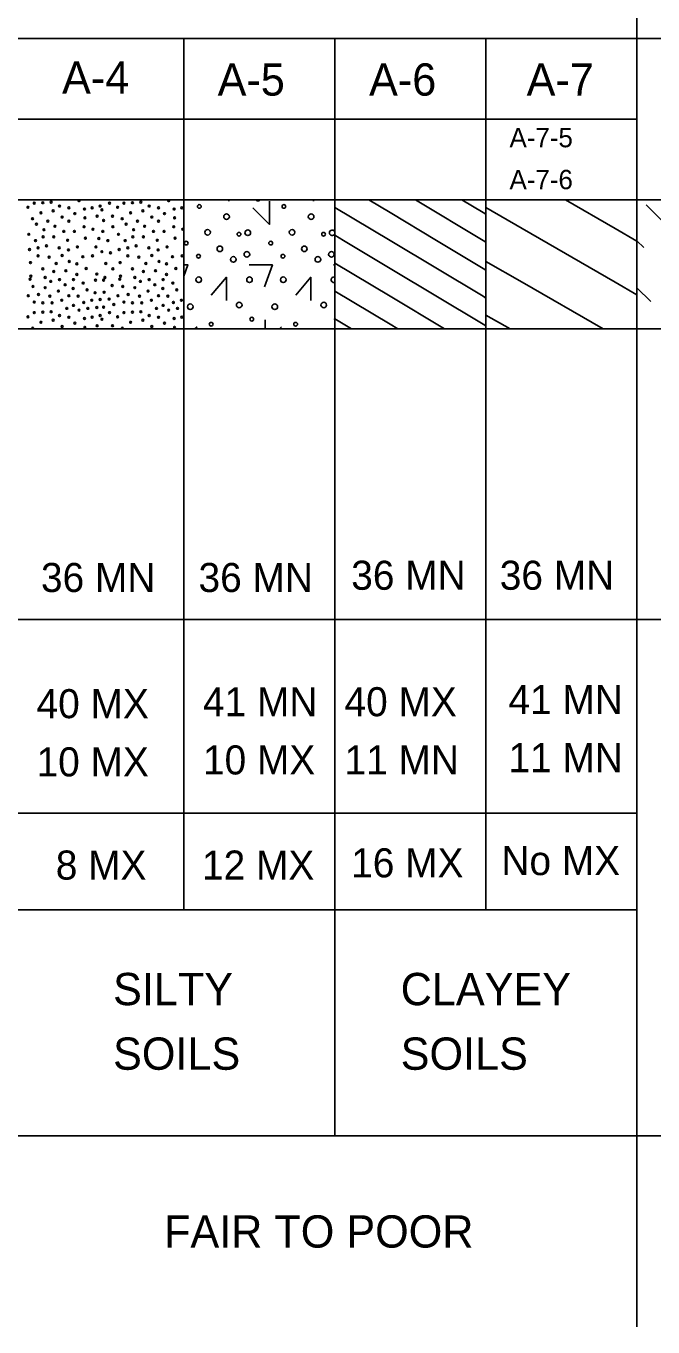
# Model space of a CAD drawing. Extents: x 278710 to 279187, y 171464 to 171625.
# Drawn here: x 279023.58 to 279032.01, y 171537.45 to 171554.93 of the extents above; entities that cross this region are included whole.
import ezdxf

# ---------------------------------------------------------------- set-up
doc = ezdxf.new("R2010")
doc.units = 0
doc.layers.add('Geotech Sheets and Borders Cell', color=7, linetype='Continuous')

msp = doc.modelspace()

# ---------------------------------------------------------------- linework, layer by layer
at = {"layer": 'Geotech Sheets and Borders Cell'}
for p, q in [((279031.791, 171556.932), (279031.791, 171537.446)), ((279031.791, 171556.932), (279031.791, 171552.486)), ((279005.33, 171554.763), (279043.07, 171554.763)), ((279025.701, 171543.051), (279025.701, 171554.763)), ((279027.731, 171548.529), (279027.731, 171554.763)), ((279029.761, 171543.051), (279029.761, 171554.763)), ((279009.451, 171553.679), (279031.791, 171553.679)), ((279005.33, 171552.594), (279043.07, 171552.594)), ((279027.731, 171552.493), (279028.473, 171552.048)), ((279028.188, 171552.594), (279028.473, 171552.423)), ((279028.813, 171552.594), (279029.723, 171552.048)), ((279029.438, 171552.594), (279029.723, 171552.423)), ((279030.247, 171552.209), (279029.761, 171552.49)), ((279031.497, 171552.209), (279030.831, 171552.594)), ((279031.791, 171546.955), (279031.791, 171552.464)), ((279032.125, 171552.316), (279031.913, 171552.529)), ((279028.473, 171552.423), (279029.097, 171552.048)), ((279029.723, 171552.423), (279029.761, 171552.4)), ((279027.731, 171552.118), (279027.847, 171552.048)), ((279031.497, 171551.487), (279030.247, 171552.209)), ((279031.791, 171552.04), (279031.497, 171552.209)), ((279027.847, 171552.048), (279028.473, 171551.673)), ((279028.473, 171552.048), (279029.723, 171551.298)), ((279029.097, 171552.048), (279029.723, 171551.673)), ((279029.723, 171552.048), (279029.761, 171552.025)), ((279031.883, 171551.952), (279031.791, 171552.043)), ((279027.731, 171551.743), (279028.473, 171551.298)), ((279030.247, 171551.487), (279029.761, 171551.768)), ((279028.473, 171551.673), (279029.723, 171550.923)), ((279029.723, 171551.673), (279029.761, 171551.65)), ((279031.335, 171550.859), (279030.247, 171551.487)), ((279031.791, 171551.318), (279031.497, 171551.487)), ((279031.978, 171551.228), (279031.791, 171551.414)), ((279027.731, 171551.368), (279028.473, 171550.923)), ((279028.473, 171551.298), (279029.204, 171550.859)), ((279029.723, 171551.298), (279029.761, 171551.275)), ((279030.085, 171550.859), (279029.761, 171551.046)), ((279005.33, 171550.859), (279043.07, 171550.859)), ((279027.731, 171550.993), (279027.954, 171550.859)), ((279028.473, 171550.923), (279028.579, 171550.859)), ((279029.723, 171550.923), (279029.761, 171550.9)), ((279027.731, 171540.014), (279027.731, 171548.703)), ((279005.33, 171546.955), (279043.07, 171546.955)), ((279005.33, 171544.352), (279031.791, 171544.352)), ((279005.33, 171543.051), (279031.791, 171543.051)), ((279005.33, 171540.014), (279043.07, 171540.014))]:
    msp.add_line(p, q, dxfattribs=at)
for points in [[(279026.306, 171552.576), (279026.306, 171552.594)], [(279026.851, 171552.576), (279026.851, 171552.264), (279026.629, 171552.485)], [(279027.442, 171552.576), (279027.442, 171552.594)], [(279025.701, 171551.719), (279025.756, 171551.719), (279025.701, 171551.567)], [(279026.579, 171551.719), (279026.892, 171551.719), (279026.784, 171551.425)], [(279027.715, 171551.719), (279027.731, 171551.719)], [(279026.273, 171551.242), (279026.273, 171551.555), (279026.071, 171551.315)], [(279027.408, 171551.242), (279027.408, 171551.555), (279027.207, 171551.315)], [(279025.85, 171550.859), (279025.88, 171550.889)], [(279026.794, 171550.98), (279026.794, 171550.859)], [(279026.986, 171550.859), (279027.016, 171550.889)]]:
    msp.add_lwpolyline(points, dxfattribs=at)
for centre, radius in [((279023.607, 171552.494), 0.0125), ((279023.692, 171552.551), 0.0125), ((279023.782, 171552.42), 0.0125), ((279023.806, 171552.556), 0.0125), ((279023.919, 171552.562), 0.0125), ((279023.947, 171552.448), 0.0125), ((279024.032, 171552.511), 0.0125), ((279024.157, 171552.487), 0.0125), ((279024.367, 171552.471), 0.0125), ((279024.469, 171552.488), 0.0125), ((279024.577, 171552.511), 0.0125), ((279024.602, 171552.46), 0.0125), ((279024.704, 171552.551), 0.0125), ((279024.812, 171552.494), 0.0125), ((279024.897, 171552.551), 0.0125), ((279024.987, 171552.42), 0.0125), ((279025.011, 171552.556), 0.0125), ((279025.124, 171552.562), 0.0125), ((279025.152, 171552.448), 0.0125), ((279025.237, 171552.511), 0.0125), ((279025.362, 171552.487), 0.0125), ((279025.572, 171552.471), 0.0125), ((279025.674, 171552.488), 0.0125), ((279025.91, 171552.506), 0.025), ((279027.046, 171552.506), 0.025), ((279023.669, 171552.341), 0.0125), ((279023.721, 171552.267), 0.0125), ((279023.874, 171552.307), 0.0125), ((279024.066, 171552.363), 0.0125), ((279024.157, 171552.307), 0.0125), ((279024.237, 171552.409), 0.0125), ((279024.373, 171552.352), 0.0125), ((279024.537, 171552.374), 0.0125), ((279024.624, 171552.318), 0.0125), ((279024.744, 171552.374), 0.0125), ((279024.874, 171552.341), 0.0125), ((279024.926, 171552.267), 0.0125), ((279025.079, 171552.307), 0.0125), ((279025.271, 171552.363), 0.0125), ((279025.362, 171552.307), 0.0125), ((279025.442, 171552.409), 0.0125), ((279025.578, 171552.352), 0.0125), ((279026.276, 171552.368), 0.0375), ((279027.412, 171552.368), 0.0375), ((279023.618, 171552.131), 0.0125), ((279023.811, 171552.097), 0.0125), ((279023.822, 171552.193), 0.0125), ((279023.953, 171552.097), 0.0125), ((279023.97, 171552.239), 0.0125), ((279024.089, 171552.171), 0.0125), ((279024.231, 171552.171), 0.0125), ((279024.361, 171552.233), 0.0125), ((279024.379, 171552.079), 0.0125), ((279024.481, 171552.199), 0.0125), ((279024.56, 171552.074), 0.0125), ((279024.613, 171552.171), 0.0125), ((279024.749, 171552.233), 0.0125), ((279024.823, 171552.131), 0.0125), ((279025.016, 171552.097), 0.0125), ((279025.027, 171552.193), 0.0125), ((279025.158, 171552.097), 0.0125), ((279025.175, 171552.239), 0.0125), ((279025.294, 171552.171), 0.0125), ((279025.436, 171552.171), 0.0125), ((279025.566, 171552.233), 0.0125), ((279025.584, 171552.079), 0.0125), ((279025.686, 171552.199), 0.0125), ((279026.021, 171552.158), 0.0375), ((279026.443, 171552.132), 0.025), ((279026.561, 171552.152), 0.0375), ((279027.156, 171552.158), 0.0375), ((279027.579, 171552.132), 0.025), ((279023.629, 171551.926), 0.0125), ((279023.709, 171552.046), 0.0125), ((279023.743, 171551.949), 0.0125), ((279023.856, 171551.977), 0.0125), ((279024.027, 171551.949), 0.0125), ((279024.14, 171552.051), 0.0125), ((279024.151, 171551.921), 0.0125), ((279024.271, 171551.961), 0.0125), ((279024.521, 171551.961), 0.0125), ((279024.602, 171551.898), 0.0125), ((279024.681, 171552.046), 0.0125), ((279024.834, 171551.926), 0.0125), ((279024.914, 171552.046), 0.0125), ((279024.948, 171551.949), 0.0125), ((279025.061, 171551.977), 0.0125), ((279025.232, 171551.949), 0.0125), ((279025.345, 171552.051), 0.0125), ((279025.356, 171551.921), 0.0125), ((279025.476, 171551.961), 0.0125), ((279025.734, 171552.013), 0.025), ((279026.186, 171551.936), 0.0375), ((279026.869, 171552.013), 0.025), ((279027.321, 171551.936), 0.0375), ((279023.641, 171551.751), 0.0125), ((279023.743, 171551.841), 0.0125), ((279023.891, 171551.824), 0.0125), ((279023.987, 171551.739), 0.0125), ((279024.066, 171551.847), 0.0125), ((279024.163, 171551.767), 0.0125), ((279024.265, 171551.734), 0.0125), ((279024.344, 171551.83), 0.0125), ((279024.475, 171551.841), 0.0125), ((279024.653, 171551.739), 0.0125), ((279024.716, 171551.881), 0.0125), ((279024.846, 171551.751), 0.0125), ((279024.948, 171551.841), 0.0125), ((279025.096, 171551.824), 0.0125), ((279025.192, 171551.739), 0.0125), ((279025.271, 171551.847), 0.0125), ((279025.368, 171551.767), 0.0125), ((279025.47, 171551.734), 0.0125), ((279025.549, 171551.83), 0.0125), ((279025.68, 171551.841), 0.0125), ((279025.899, 171551.836), 0.025), ((279026.367, 171551.794), 0.0375), ((279026.549, 171551.862), 0.0375), ((279027.034, 171551.836), 0.025), ((279027.503, 171551.794), 0.0375), ((279027.685, 171551.862), 0.0375), ((279023.647, 171551.569), 0.0125), ((279023.806, 171551.666), 0.0125), ((279023.839, 171551.552), 0.0125), ((279023.953, 171551.631), 0.0125), ((279024.117, 171551.642), 0.0125), ((279024.265, 171551.592), 0.0125), ((279024.39, 171551.671), 0.0125), ((279024.532, 171551.597), 0.0125), ((279024.642, 171551.552), 0.0125), ((279024.749, 171551.666), 0.0125), ((279024.852, 171551.569), 0.0125), ((279025.011, 171551.666), 0.0125), ((279025.044, 171551.552), 0.0125), ((279025.158, 171551.631), 0.0125), ((279025.322, 171551.642), 0.0125), ((279025.47, 171551.592), 0.0125), ((279025.595, 171551.671), 0.0125), ((279025.902, 171551.521), 0.0375), ((279026.584, 171551.521), 0.0375), ((279027.038, 171551.521), 0.0375), ((279023.635, 171551.527), 0.0125), ((279023.675, 171551.431), 0.0125), ((279023.839, 171551.414), 0.0125), ((279023.913, 171551.499), 0.0125), ((279024.016, 171551.369), 0.0125), ((279024.032, 171551.522), 0.0125), ((279024.106, 171551.454), 0.0125), ((279024.214, 171551.402), 0.0125), ((279024.219, 171551.522), 0.0125), ((279024.35, 171551.476), 0.0125), ((279024.401, 171551.386), 0.0125), ((279024.515, 171551.516), 0.0125), ((279024.624, 171551.516), 0.0125), ((279024.738, 171551.442), 0.0125), ((279024.84, 171551.527), 0.0125), ((279024.88, 171551.431), 0.0125), ((279025.044, 171551.414), 0.0125), ((279025.118, 171551.499), 0.0125), ((279025.221, 171551.369), 0.0125), ((279025.237, 171551.522), 0.0125), ((279025.311, 171551.454), 0.0125), ((279025.419, 171551.402), 0.0125), ((279025.424, 171551.522), 0.0125), ((279025.555, 171551.476), 0.0125), ((279025.606, 171551.386), 0.0125), ((279023.612, 171551.306), 0.0125), ((279023.692, 171551.221), 0.0125), ((279023.749, 171551.323), 0.0125), ((279023.806, 171551.21), 0.0125), ((279023.902, 171551.301), 0.0125), ((279023.931, 171551.21), 0.0125), ((279024.061, 171551.244), 0.0125), ((279024.157, 171551.306), 0.0125), ((279024.282, 171551.301), 0.0125), ((279024.356, 171551.216), 0.0125), ((279024.464, 171551.244), 0.0125), ((279024.509, 171551.346), 0.0125), ((279024.577, 171551.255), 0.0125), ((279024.631, 171551.352), 0.0125), ((279024.698, 171551.261), 0.0125), ((279024.817, 171551.306), 0.0125), ((279024.897, 171551.221), 0.0125), ((279024.954, 171551.323), 0.0125), ((279025.011, 171551.21), 0.0125), ((279025.107, 171551.301), 0.0125), ((279025.136, 171551.21), 0.0125), ((279025.266, 171551.244), 0.0125), ((279025.362, 171551.306), 0.0125), ((279025.487, 171551.301), 0.0125), ((279025.561, 171551.216), 0.0125), ((279025.669, 171551.244), 0.0125), ((279026.446, 171551.181), 0.0375), ((279027.582, 171551.181), 0.0375), ((279023.607, 171551.022), 0.0125), ((279023.692, 171551.079), 0.0125), ((279023.806, 171551.085), 0.0125), ((279023.919, 171551.091), 0.0125), ((279024.032, 171551.039), 0.0125), ((279024.129, 171551.136), 0.0125), ((279024.219, 171551.176), 0.0125), ((279024.293, 171551.113), 0.0125), ((279024.412, 171551.136), 0.0125), ((279024.532, 171551.147), 0.0125), ((279024.577, 171551.039), 0.0125), ((279024.624, 171551.153), 0.0125), ((279024.704, 171551.079), 0.0125), ((279024.761, 171551.187), 0.0125), ((279024.812, 171551.022), 0.0125), ((279024.897, 171551.079), 0.0125), ((279025.011, 171551.085), 0.0125), ((279025.124, 171551.091), 0.0125), ((279025.237, 171551.039), 0.0125), ((279025.334, 171551.136), 0.0125), ((279025.424, 171551.176), 0.0125), ((279025.498, 171551.113), 0.0125), ((279025.617, 171551.136), 0.0125), ((279025.788, 171551.158), 0.0375), ((279026.924, 171551.158), 0.0375), ((279023.782, 171550.949), 0.0125), ((279023.947, 171550.977), 0.0125), ((279024.066, 171550.892), 0.0125), ((279024.157, 171551.016), 0.0125), ((279024.237, 171550.937), 0.0125), ((279024.367, 171551), 0.0125), ((279024.373, 171550.881), 0.0125), ((279024.469, 171551.017), 0.0125), ((279024.537, 171550.903), 0.0125), ((279024.602, 171550.989), 0.0125), ((279024.744, 171550.903), 0.0125), ((279024.987, 171550.949), 0.0125), ((279025.152, 171550.977), 0.0125), ((279025.271, 171550.892), 0.0125), ((279025.362, 171551.016), 0.0125), ((279025.442, 171550.937), 0.0125), ((279025.572, 171551), 0.0125), ((279025.578, 171550.881), 0.0125), ((279025.674, 171551.017), 0.0125), ((279026.069, 171550.923), 0.025), ((279026.614, 171550.991), 0.025), ((279027.204, 171550.923), 0.025)]:
    msp.add_circle(centre, radius, dxfattribs=at)
for centre, radius, start, end in [((279024.293, 171552.584), 0.0125, 128.4735, 51.5265), ((279025.498, 171552.584), 0.0125, 128.4735, 51.5265), ((279026.697, 171552.617), 0.0375, 217.8115, 322.1885), ((279027.696, 171552.152), 0.0375, 22.8613, 337.1387), ((279027.719, 171551.521), 0.0375, 72.255, 287.745), ((279023.669, 171550.869), 0.0125, 305.1764, 234.8236), ((279024.624, 171550.847), 0.0125, 79.3017, 100.6983), ((279024.874, 171550.869), 0.0125, 305.1764, 234.8236), ((279027.75, 171550.991), 0.025, 140.1592, 219.8408)]:
    msp.add_arc(centre, radius, start, end, dxfattribs=at)

# ---------------------------------------------------------------- texts
for s, height, p in [('A-4', 0.4338, (279024.065, 171554.021)), ('A-5', 0.4338, (279026.156, 171553.995)), ('A-6', 0.4338, (279028.191, 171553.995)), ('A-7', 0.4338, (279030.308, 171553.995)), ('A-7-5', 0.2603, (279030.078, 171553.301)), ('A-7-6', 0.2603, (279030.078, 171552.737)), ('36 MN', 0.3904, (279023.782, 171547.324)), ('36 MN', 0.3904, (279025.899, 171547.324)), ('36 MN', 0.3904, (279027.951, 171547.354)), ('36 MN', 0.3904, (279029.947, 171547.354)), ('40 MX', 0.3904, (279023.723, 171545.628)), ('41 MN', 0.3904, (279025.959, 171545.654)), ('40 MX', 0.3904, (279027.861, 171545.654)), ('41 MN', 0.3904, (279030.064, 171545.684)), ('10 MX', 0.3904, (279025.959, 171544.872)), ('11 MN', 0.3904, (279027.861, 171544.872)), ('11 MN', 0.3904, (279030.064, 171544.902)), ('10 MX', 0.3904, (279023.723, 171544.846)), ('16 MX', 0.3904, (279027.95, 171543.489)), ('No MX', 0.3904, (279029.969, 171543.519)), ('8 MX', 0.3904, (279023.981, 171543.459)), ('12 MX', 0.3904, (279025.946, 171543.459)), ('SILTY', 0.4338, (279024.751, 171541.771)), ('CLAYEY', 0.4338, (279028.616, 171541.771)), ('SOILS', 0.4338, (279024.751, 171540.903)), ('SOILS', 0.4338, (279028.616, 171540.903)), ('FAIR TO POOR', 0.43381, (279025.436, 171538.513))]:
    msp.add_text(s, height=height, dxfattribs=at).set_placement(p)

doc.saveas('drawing.dxf')
